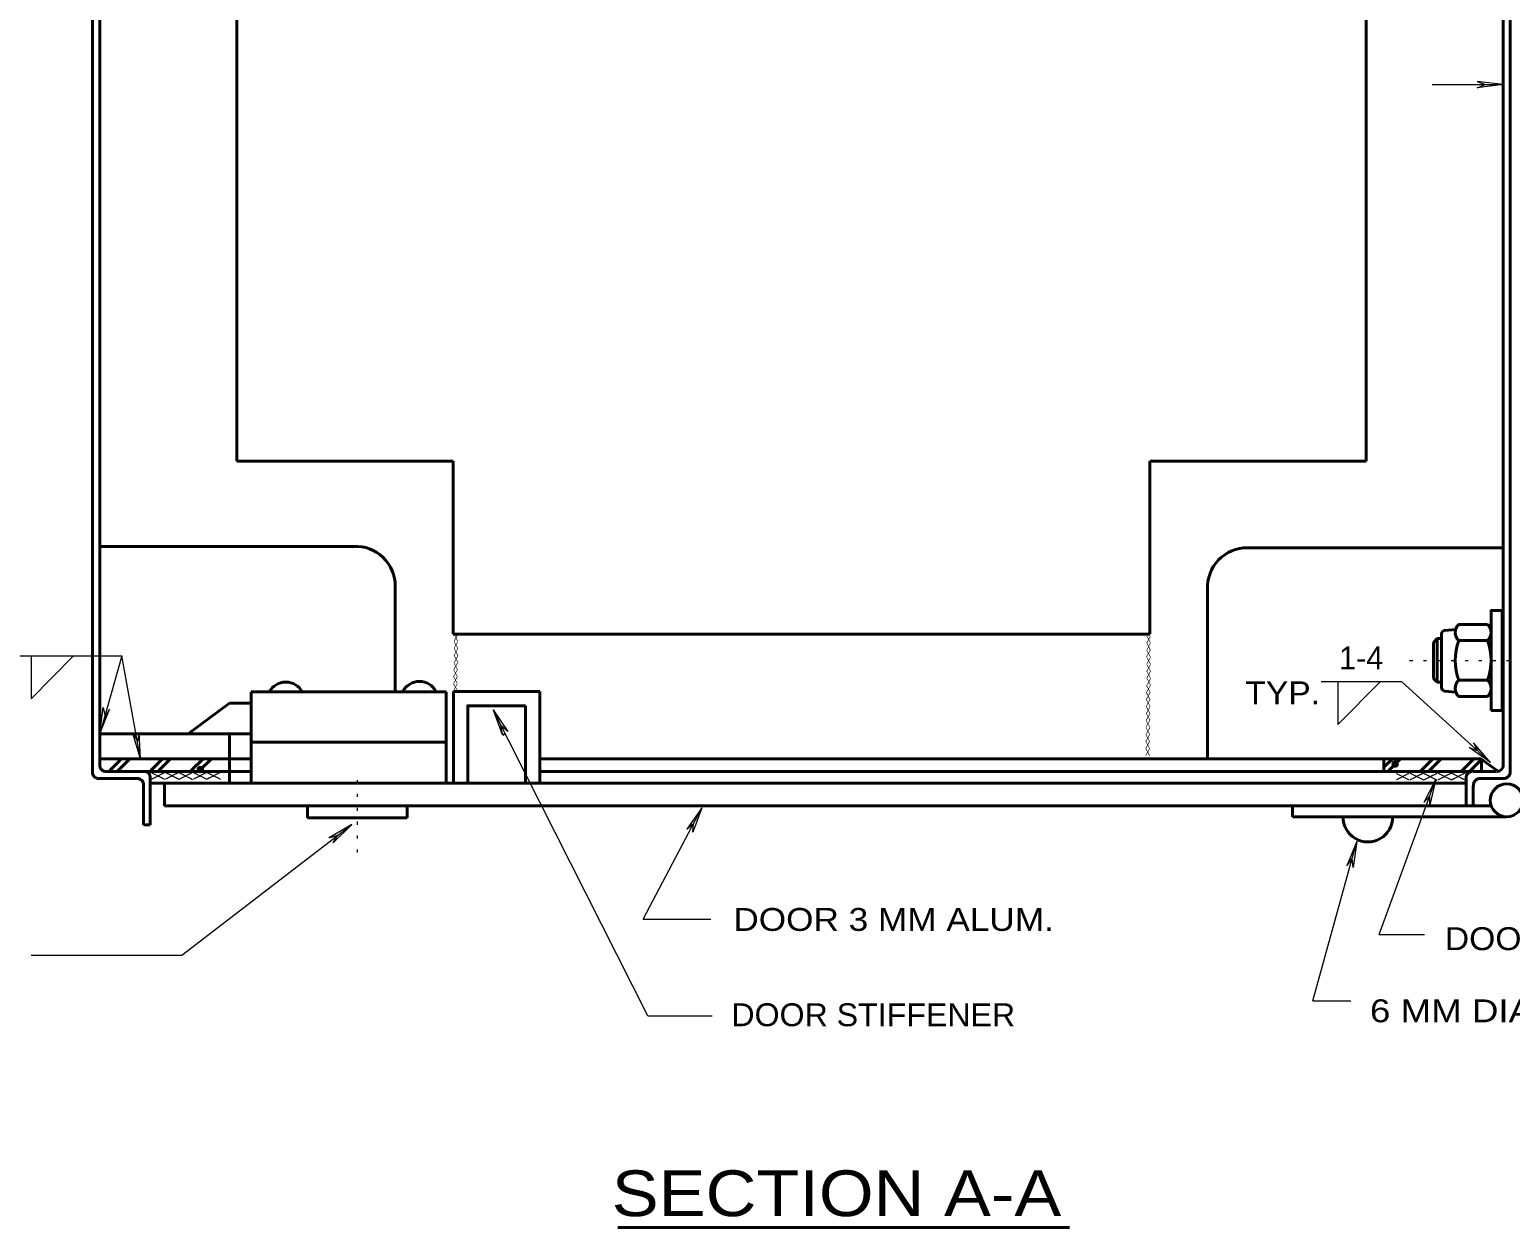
# Model space of a CAD drawing. Extents: x 312583 to 312853, y 144420 to 144585.
# Drawn here: x 312761.34 to 312810.54, y 144503.73 to 144543.53 of the extents above; entities that cross this region are included whole.
import ezdxf
from ezdxf.enums import TextEntityAlignment as Align

# ---------------------------------------------------------------- set-up
doc = ezdxf.new("R2010")
doc.units = 0
doc.header["$LTSCALE"] = 0.3
doc.header["$PDMODE"] = 32
doc.header["$PDSIZE"] = 0.15
doc.linetypes.add('DOTTED', pattern=[1.5, 0.3, -1.2])
doc.layers.add('1', color=7, linetype='Continuous', lineweight=40)
doc.layers.add('2', color=7, linetype='Continuous', lineweight=13)

msp = doc.modelspace()

# ---------------------------------------------------------------- linework, layer by layer
at = {"layer": '1'}
for p, q in [((312772.2426, 144526.3588), (312763.6712, 144526.3588)), ((312810.2692, 144520.9078), (312810.2692, 144524.2274)), ((312808.3526, 144523.5681), (312808.7359, 144523.5911)), ((312808.8202, 144523.7674), (312809.7862, 144523.7674)), ((312810.2692, 144521.4904), (312810.2692, 144523.6448)), ((312807.9846, 144523.1694), (312808.1072, 144523.2921)), ((312807.9846, 144521.9658), (312807.9846, 144523.1694)), ((312808.1072, 144521.8431), (312808.1072, 144523.2921)), ((312808.2606, 144523.2921), (312808.1072, 144523.2921)), ((312808.2529, 144521.6438), (312808.2529, 144523.4608)), ((312808.8202, 144523.2308), (312809.7862, 144523.2308)), ((312807.9846, 144521.9658), (312808.1072, 144521.8431)), ((312808.2529, 144521.8431), (312808.1072, 144521.8431)), ((312808.3679, 144521.5441), (312808.7129, 144521.5134)), ((312808.8202, 144521.9121), (312809.7862, 144521.9121)), ((312808.8202, 144521.9121), (312809.7862, 144521.9121)), ((312767.9799, 144521.1454), (312766.6076, 144520.1334)), ((312808.8202, 144521.3678), (312809.7862, 144521.3678)), ((312809.9012, 144520.9078), (312810.2692, 144520.9078)), ((312768.7006, 144520.1334), (312763.6712, 144520.1334)), ((312764.0086, 144518.9144), (312764.3996, 144519.3054)), ((312764.6679, 144519.3054), (312764.2462, 144518.8838)), ((312765.3656, 144518.9144), (312765.7566, 144519.3054)), ((312765.6339, 144518.9144), (312766.0249, 144519.3054)), ((312766.7149, 144518.9144), (312767.1059, 144519.3054)), ((312766.9909, 144518.9144), (312767.3819, 144519.3054)), ((312806.3362, 144518.8838), (312806.3362, 144519.3054)), ((312806.3362, 144519.0218), (312806.6199, 144519.3054)), ((312806.4666, 144518.8838), (312806.8882, 144519.3054)), ((312807.9692, 144519.3054), (312807.5476, 144518.8838)), ((312807.8236, 144518.8838), (312808.2452, 144519.3054)), ((312808.9046, 144518.8838), (312809.3262, 144519.3054)), ((312809.1806, 144518.8838), (312809.6022, 144519.3054)), ((312809.5639, 144519.3054), (312810.1159, 144518.9068)), ((312809.5869, 144518.8838), (312809.5869, 144519.2518)), ((312765.3502, 144518.6461), (312765.3502, 144517.1051)), ((312809.9012, 144517.7338), (312765.8256, 144517.7338)), ((312803.3002, 144517.7338), (312803.3002, 144517.3734)), ((312773.8909, 144517.3351), (312770.5789, 144517.3351)), ((312810.4149, 144517.3734), (312803.3002, 144517.3734))]:
    msp.add_line(p, q, dxfattribs=at)
at = {"layer": '1', "linetype": 'DOTTED', "lineweight": 13}
for p, q in [((312807.1949, 144522.5714), (312812.1169, 144522.5714)), ((312772.2349, 144516.1928), (312772.2349, 144518.7534))]:
    msp.add_line(p, q, dxfattribs=at)
at = {"layer": '1'}
msp.add_lwpolyline([(312809.9012, 144520.9078), (312809.9012, 144524.2274), (312810.2692, 144524.2274)], dxfattribs=at)
msp.add_circle((312810.4214, 144517.9217), 0.5474, dxfattribs=at)
for centre, radius, start, end in [((312772.1689, 144525.0374), 1.3235, 353.7996, 86.80746), ((312801.8003, 144524.9894), 1.3235, 83.7996, 176.80746), ((312808.3935, 144523.4319), 0.1422, 106.73817, 171.43306), ((312809.0687, 144523.4963), 0.363, 132.07502, 227.92498), ((312809.5402, 144523.4963), 0.363, 312.07502, 47.92498), ((312810.5767, 144522.5683), 1.871, 159.39031, 200.60969), ((312808.0322, 144522.5683), 1.871, 339.39031, 20.60969), ((312769.8544, 144521.2302), 0.6206, 27.9529, 152.0471), ((312774.2934, 144521.2532), 0.6206, 27.9529, 152.0471), ((312808.3891, 144521.6847), 0.1422, 196.73817, 261.43306), ((312809.0687, 144521.6402), 0.363, 132.07502, 227.92498), ((312809.5402, 144521.6402), 0.363, 312.07502, 47.92498), ((312805.8056, 144517.3583), 0.8211, 179.38614, 0.61167)]:
    msp.add_arc(centre, radius, start, end, dxfattribs=at)
for p in [(312806.7119, 144519.1291), (312767.0139, 144518.9451)]:
    msp.add_point(p, dxfattribs=at)
at = {"layer": '2', "lineweight": 40}
for p, q in [((312763.4336, 144540.9254), (312763.4336, 144562.9671)), ((312810.5376, 144562.9671), (312810.5376, 144518.8838)), ((312763.6712, 144540.9254), (312763.6712, 144562.7448)), ((312810.2999, 144540.9254), (312810.2999, 144562.7448)), ((312768.2252, 144529.1878), (312768.2252, 144552.6631)), ((312805.7459, 144552.6631), (312805.7459, 144529.1878)), ((312763.4336, 144540.9254), (312763.4336, 144518.8684)), ((312763.6712, 144540.9254), (312763.6712, 144519.1061)), ((312810.2999, 144540.9254), (312810.2999, 144519.1061)), ((312768.2252, 144529.1878), (312775.4166, 144529.1878)), ((312775.4166, 144523.4378), (312775.4166, 144529.1878)), ((312798.5622, 144529.1878), (312805.7459, 144529.1878)), ((312798.5622, 144523.4378), (312798.5622, 144529.1878)), ((312810.2999, 144526.3128), (312801.8742, 144526.3128)), ((312800.4789, 144519.3054), (312800.4789, 144525.0631)), ((312773.4922, 144524.9634), (312773.4922, 144521.5211)), ((312775.4166, 144523.4378), (312798.5622, 144523.4378)), ((312775.4242, 144521.5364), (312778.2992, 144521.5364)), ((312775.4242, 144518.4928), (312775.4242, 144521.5364)), ((312778.2992, 144518.4928), (312778.2992, 144521.5364)), ((312767.9799, 144521.1454), (312768.7006, 144521.1454)), ((312768.7006, 144521.5211), (312768.7006, 144518.4928)), ((312768.7006, 144521.5211), (312775.1789, 144521.5211)), ((312775.1789, 144521.5211), (312775.1789, 144518.4928)), ((312777.8162, 144518.4928), (312777.8162, 144521.0611)), ((312767.9799, 144520.1334), (312767.9799, 144518.4928)), ((312768.7006, 144519.8498), (312775.1789, 144519.8498)), ((312768.7006, 144519.3054), (312763.6712, 144519.3054)), ((312809.5639, 144519.3054), (312778.2992, 144519.3054)), ((312763.6099, 144518.6461), (312764.9439, 144518.6461)), ((312763.8476, 144518.8838), (312765.1739, 144518.8838)), ((312764.5759, 144518.8838), (312768.7006, 144518.8838)), ((312778.2992, 144518.8838), (312786.9856, 144518.8838)), ((312809.2572, 144518.8838), (312786.9856, 144518.8838)), ((312809.0732, 144517.7338), (312809.0732, 144518.6691)), ((312810.0622, 144518.8838), (312809.3186, 144518.8838)), ((312810.2999, 144518.6461), (312809.5562, 144518.6461)), ((312765.1202, 144518.4238), (312765.1202, 144517.1051)), ((312765.3732, 144518.4928), (312787.0086, 144518.4928)), ((312765.8256, 144517.7338), (312765.8256, 144518.4928)), ((312809.0886, 144518.4928), (312787.0086, 144518.4928)), ((312809.3032, 144517.7338), (312809.3032, 144518.4084)), ((312770.5789, 144517.3351), (312770.5789, 144517.7338)), ((312773.8909, 144517.3351), (312773.8909, 144517.7338)), ((312765.1202, 144517.1051), (312765.3502, 144517.1051)), ((312780.8829, 144503.7344), (312795.8969, 144503.7344))]:
    msp.add_line(p, q, dxfattribs=at)
at = {"layer": '2'}
for p, q in [((312809.4336, 144541.8071), (312809.7096, 144541.6998)), ((312810.2999, 144541.6998), (312809.4336, 144541.8071)), ((312807.9386, 144541.6998), (312810.2999, 144541.6998)), ((312809.4336, 144541.5924), (312809.7096, 144541.6998)), ((312810.2999, 144541.6998), (312809.4336, 144541.5924)), ((312759.5082, 144522.7171), (312764.4072, 144522.7171)), ((312761.3942, 144521.2911), (312762.8049, 144522.7171)), ((312761.3942, 144522.7171), (312761.3942, 144521.2911)), ((312764.4072, 144522.7171), (312763.6712, 144520.1334)), ((312765.0206, 144519.3054), (312764.4072, 144522.7171)), ((312804.2586, 144521.8661), (312806.9189, 144521.8661)), ((312804.8106, 144520.4401), (312806.2212, 144521.8661)), ((312804.8106, 144521.8661), (312804.8106, 144520.4401)), ((312806.9189, 144521.8661), (312809.8859, 144519.1751)), ((312763.6712, 144520.1334), (312763.7862, 144521.0074)), ((312763.6712, 144520.1334), (312764.0009, 144520.9461)), ((312763.7862, 144521.0074), (312763.8476, 144520.6931)), ((312764.0009, 144520.9461), (312763.8476, 144520.6931)), ((312781.8872, 144510.7571), (312776.7429, 144520.9308)), ((312776.7429, 144520.9308), (312777.0419, 144520.1104)), ((312776.7429, 144520.9308), (312777.2259, 144520.2101)), ((312764.7676, 144520.1411), (312764.9209, 144519.8881)), ((312765.0206, 144519.3054), (312764.7676, 144520.1411)), ((312764.9822, 144520.1718), (312764.9209, 144519.8881)), ((312765.0206, 144519.3054), (312764.9822, 144520.1718)), ((312777.0419, 144520.1104), (312777.0112, 144520.4018)), ((312777.2259, 144520.2101), (312777.0112, 144520.4018)), ((312809.1729, 144519.6811), (312809.4489, 144519.5738)), ((312809.8859, 144519.1751), (312809.1729, 144519.6811)), ((312809.3186, 144519.8344), (312809.4489, 144519.5738)), ((312809.8859, 144519.1751), (312809.3186, 144519.8344)), ((312806.1829, 144513.4634), (312808.0612, 144518.6231)), ((312808.0612, 144518.6231), (312807.6626, 144517.8488)), ((312808.0612, 144518.6231), (312807.8696, 144517.7721)), ((312781.7262, 144513.9694), (312783.6812, 144517.6724)), ((312783.6812, 144517.6724), (312783.1829, 144516.9594)), ((312783.6812, 144517.6724), (312783.3746, 144516.8598)), ((312807.6626, 144517.8488), (312807.8619, 144518.0711)), ((312807.8696, 144517.7721), (312807.8619, 144518.0711)), ((312766.4006, 144512.7811), (312772.0509, 144517.1204)), ((312772.0509, 144517.1204), (312771.2996, 144516.6758)), ((312772.0509, 144517.1204), (312771.4299, 144516.5071)), ((312783.1829, 144516.9594), (312783.4052, 144517.1511)), ((312783.3746, 144516.8598), (312783.4052, 144517.1511)), ((312771.2996, 144516.6758), (312771.5832, 144516.7601)), ((312771.4299, 144516.5071), (312771.5832, 144516.7601)), ((312803.9826, 144511.2631), (312805.4392, 144516.5531)), ((312805.4392, 144516.5531), (312805.1096, 144515.7481)), ((312805.4392, 144516.5531), (312805.3166, 144515.6868)), ((312805.1096, 144515.7481), (312805.2859, 144515.9858)), ((312805.3166, 144515.6868), (312805.2859, 144515.9858)), ((312781.7262, 144513.9694), (312783.9802, 144513.9694)), ((312806.1829, 144513.4634), (312807.6856, 144513.4634)), ((312761.3942, 144512.7811), (312766.4006, 144512.7811)), ((312803.9826, 144511.2631), (312805.2399, 144511.2631)), ((312781.8872, 144510.7571), (312784.0186, 144510.7571))]:
    msp.add_line(p, q, dxfattribs=at)
at = {"layer": '2', "lineweight": 40}
msp.add_lwpolyline([(312775.8996, 144518.4928), (312775.8996, 144521.0611), (312777.8162, 144521.0611)], dxfattribs=at)
at = {"layer": '2'}
msp.add_lwpolyline([(312777.0419, 144520.1718), (312777.0802, 144520.0874), (312777.1262, 144520.1258)], dxfattribs=at)
at = {"layer": '2', "lineweight": 40}
for centre, radius, start, end in [((312763.8706, 144519.0831), 0.2007, 173.41806, 276.58194), ((312810.1006, 144519.0831), 0.2007, 263.41806, 6.58194), ((312763.6329, 144518.8454), 0.2007, 173.41806, 276.58194), ((312764.9209, 144518.4468), 0.2007, 353.41806, 96.58194), ((312765.1509, 144518.6844), 0.2007, 353.41806, 96.58194), ((312809.2967, 144518.668), 0.2239, 84.40066, 183.64627), ((312809.5343, 144518.4227), 0.2239, 84.40066, 183.64627), ((312810.3141, 144518.8695), 0.2239, 264.40066, 3.64627)]:
    msp.add_arc(centre, radius, start, end, dxfattribs=at)

# ---------------------------------------------------------------- texts
at = {"layer": '1', "width": 0.7}
for height, p in [(0.23, (312775.4242, 144523.2001)), (0.23, (312775.4242, 144522.9624)), (0.23, (312798.4396, 144523.1464)), (0.2377, (312798.4396, 144522.9088)), (0.23, (312775.4242, 144522.7324)), (0.23, (312775.4319, 144522.4948)), (0.23, (312798.4319, 144522.6864)), (0.23, (312798.4396, 144522.4411)), (0.23, (312775.4089, 144522.0271)), (0.23, (312775.4166, 144522.2571)), (0.23, (312798.4396, 144522.2034)), (0.23, (312798.4396, 144521.9734)), (0.23, (312775.4089, 144521.7971)), (0.23, (312775.4089, 144521.5594)), (0.23, (312798.4319, 144521.4981)), (0.23, (312798.4472, 144521.7358)), (0.23, (312798.4242, 144521.2681)), (0.23, (312798.4242, 144521.0381)), (0.23, (312798.4166, 144520.3481)), (0.23, (312798.4242, 144520.8004)), (0.23, (312798.4242, 144520.5781)), (0.23, (312798.4089, 144519.8728)), (0.23, (312798.4166, 144520.1028)), (0.23, (312798.4089, 144519.6428)), (0.23, (312798.4089, 144519.4051))]:
    msp.add_text('X', height=height, dxfattribs=at).set_placement(p)
at = {"layer": '1', "width": 0.75}
for height, p in [(0.437, (312765.8332, 144518.5848)), (0.4524, (312766.3086, 144518.5848)), (0.4523, (312766.7609, 144518.5771)), (0.4523, (312767.2362, 144518.5848)), (0.4524, (312767.6886, 144518.5848)), (0.437, (312807.1872, 144518.5618)), (0.4524, (312807.6626, 144518.5618)), (0.4523, (312808.1149, 144518.5541)), (0.4523, (312808.5902, 144518.5618)), (0.4524, (312809.0426, 144518.5618))]:
    msp.add_text('X', height=height, rotation=90, dxfattribs=at).set_placement(p)
at = {"layer": '2'}
msp.add_text('1-4', height=0.76, dxfattribs=at).set_placement((312804.8489, 144522.2732))
for s, width, p in [('TYP.', 1.1, (312801.7339, 144521.1124)), ('DOOR 3 MM ALUM.', 1.15, (312784.7239, 144513.5844)), ('DOOR GASKET CLOSED CELL NEOPRENE', 1.1, (312808.3644, 144512.9458)), ("6 MM DIA. RIVETS (3)  REQ'D.  EACH HINGE", 1.2, (312805.8762, 144510.5491)), ('DOOR STIFFENER', 1.05, (312784.6591, 144510.4181))]:
    msp.add_text(s, height=0.76, dxfattribs=dict(at, width=width)).set_placement(p)
at = {"layer": '2', "width": 1.15}
msp.add_text('SECTION A-A', height=1.52, dxfattribs=at).set_placement((312788.151, 144504.1072), align=Align.CENTER)

doc.saveas('drawing.dxf')
